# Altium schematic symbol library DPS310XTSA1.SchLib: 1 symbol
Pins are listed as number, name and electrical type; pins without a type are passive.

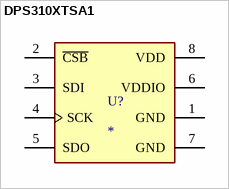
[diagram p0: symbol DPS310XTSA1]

## DPS310XTSA1
designator U?
Pressure Sensor 4.35PSI ~ 17.4PSI (30kPa ~ 120kPa) Absolute 24 b 8-VFLGA
footprint DPS310XTSA1
pins: 1 GND, 2 ~{CSB}, 3 SDI, 4 SCK, 5 SDO, 6 VDDIO, 7 GND, 8 VDD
